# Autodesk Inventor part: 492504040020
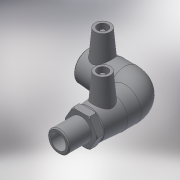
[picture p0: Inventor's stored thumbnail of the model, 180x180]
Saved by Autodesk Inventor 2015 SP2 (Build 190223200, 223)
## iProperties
Created: 2017-06
Part Number: 492504040020
Material: Generic
Description: PLASSON 90° ELBOW MALE TRANSITION 40-2"
Document SubType Name: Modeling
Designer: KIM
Mass: 239.351 g
Surface Area: 578.813 cm^2
Volume: 239.351 cm^3
Density: 1 g/cm^3
Appearance: Default
Author: KIM
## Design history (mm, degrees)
derived "492504.ipt"
feature "Solid1::492504.ipt"
tag "TaggingFeature1"
body "Solid1"
other parameters: "d2" = 56, "d4" = 30.66667, "d5" = 50.4, "d8" = 168 deg, "d10" = 17.6, "d11" = 5.86667, "d29" = 47, "d30" = 15, "d31" = 50.6, "d34" = 5 deg, "d41" = 4, "d42" = 14, "d43" = 0, "d48" = 64, "d50" = 34, "d51" = 17.6, "d52" = 44, "d54" = 90 deg, "d58" = 44, "d59" = 0, "d61" = 90 deg, "d86" = 3, "d87" = 0, "d93" = 0.1, "d94" = 10.25, "d95" = 59.614, "d96" = 41.7298, "d97" = 29, "d98" = 41, "d99" = 72.8, "d100" = 36.9, "d102" = 2, "d106" = 0, "L_" = 133, "L_1" = 44, "D_" = 29, "A_" = 47, "d_2" = 12, "L_2" = 41, "D_1" = 56, "R_" = 59.614
